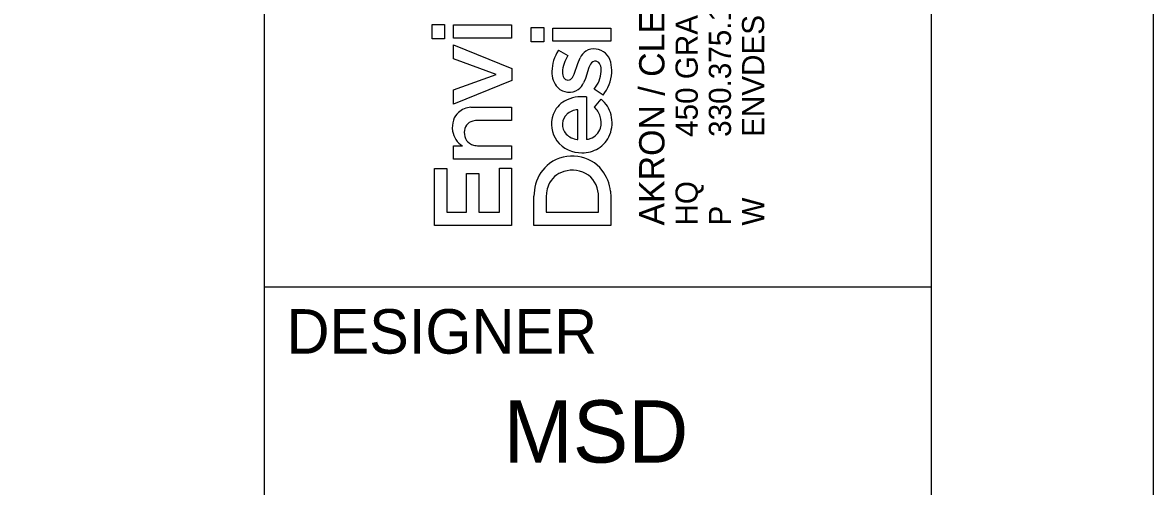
# Model space of a CAD drawing. Extents: x -6.7 to 34, y -1.6 to 22.
# Drawn here: x 31.456 to 34, y 2.552 to 3.594 of the extents above; entities that cross this region are included whole.
import ezdxf

# ---------------------------------------------------------------- set-up
doc = ezdxf.new("R2010")
doc.units = 0
for name, color, linetype in [('SH_Border', 7, 'Continuous'), ('SH_Cut_Line', 7, 'Continuous'), ('SH_Data', 7, 'Continuous')]:
    doc.layers.add(name, color=color, linetype=linetype)

msp = doc.modelspace()

# ---------------------------------------------------------------- linework, layer by layer
at = {"layer": 'SH_Border'}
for p, q in [((32, 0.5), (32, 21.5)), ((32, 3), (33.5, 3))]:
    msp.add_line(p, q, dxfattribs=at)
msp.add_lwpolyline([(1.5, 21.5), (33.5, 21.5), (33.5, 0.5), (1.5, 0.5)], close=True, dxfattribs=at)
at = {"layer": 'SH_Cut_Line'}
msp.add_lwpolyline([(0, 0), (34, 0), (34, 22), (0, 22)], close=True, dxfattribs=at)
at = {"layer": 'SH_Data'}
for p, q in [((32.3771, 3.5582), (32.3771, 3.5903)), ((32.3771, 3.5903), (32.4054, 3.5903)), ((32.4054, 3.5903), (32.4054, 3.5582)), ((32.4254, 3.5594), (32.4254, 3.5893)), ((32.4254, 3.5893), (32.5557, 3.5893)), ((32.5557, 3.5893), (32.5557, 3.5594)), ((32.6005, 3.5511), (32.6005, 3.5832)), ((32.6005, 3.5832), (32.6289, 3.5832)), ((32.6289, 3.5832), (32.6289, 3.5511)), ((32.6489, 3.5523), (32.6489, 3.5822)), ((32.6489, 3.5822), (32.7792, 3.5822)), ((32.7792, 3.5822), (32.7792, 3.5523)), ((32.4054, 3.5582), (32.3771, 3.5582)), ((32.5557, 3.5594), (32.4254, 3.5594)), ((32.4254, 3.5133), (32.4254, 3.5446)), ((32.4254, 3.5446), (32.5567, 3.4913)), ((32.6289, 3.5511), (32.6005, 3.5511)), ((32.7792, 3.5523), (32.6489, 3.5523)), ((32.5212, 3.478), (32.4254, 3.5133)), ((32.6615, 3.5321), (32.6827, 3.5203)), ((32.7048, 3.5026), (32.7104, 3.5153)), ((32.5567, 3.4913), (32.5567, 3.4644)), ((32.6967, 3.4787), (32.7048, 3.5026)), ((32.7298, 3.4933), (32.7221, 3.4688)), ((32.7334, 3.501), (32.7298, 3.4933)), ((32.4254, 3.4429), (32.5212, 3.478)), ((32.5567, 3.4644), (32.4254, 3.4109)), ((32.693, 3.4712), (32.6967, 3.4787)), ((32.7221, 3.4688), (32.7182, 3.4592)), ((32.4254, 3.4109), (32.4254, 3.4429)), ((32.7621, 3.4314), (32.742, 3.4447)), ((32.7245, 3.4275), (32.7246, 3.3319)), ((32.7423, 3.4046), (32.7577, 3.422)), ((32.4644, 3.404), (32.4729, 3.4044)), ((32.4729, 3.4044), (32.5557, 3.4044)), ((32.5557, 3.4044), (32.5557, 3.3746)), ((32.7049, 3.3318), (32.7049, 3.3983)), ((32.5557, 3.3746), (32.4814, 3.3746)), ((32.4254, 3.2875), (32.4254, 3.3173)), ((32.4254, 3.3173), (32.4455, 3.3173)), ((32.4822, 3.3173), (32.5557, 3.3173)), ((32.5557, 3.3173), (32.5557, 3.2876)), ((32.7036, 3.3317), (32.7049, 3.3318)), ((32.5557, 3.2876), (32.4254, 3.2875)), ((32.383, 3.1379), (32.383, 3.266)), ((32.383, 3.266), (32.4101, 3.266)), ((32.4101, 3.266), (32.4101, 3.1683)), ((32.5286, 3.1683), (32.5286, 3.2672)), ((32.5286, 3.2672), (32.5557, 3.2672)), ((32.5557, 3.2672), (32.5557, 3.1379)), ((32.455, 3.1683), (32.455, 3.2549)), ((32.455, 3.2549), (32.4822, 3.2549)), ((32.4822, 3.2549), (32.4822, 3.1683)), ((32.6347, 3.2118), (32.6341, 3.2023)), ((32.7785, 3.215), (32.7792, 3.2021)), ((32.6064, 3.138), (32.6064, 3.204)), ((32.6341, 3.2023), (32.6341, 3.1684)), ((32.7515, 3.1683), (32.7515, 3.2024)), ((32.7792, 3.2021), (32.7792, 3.138)), ((32.4101, 3.1683), (32.455, 3.1683)), ((32.4822, 3.1683), (32.5286, 3.1683)), ((32.6341, 3.1684), (32.7515, 3.1683)), ((32.5557, 3.1379), (32.383, 3.1379)), ((32.7792, 3.138), (32.6064, 3.138))]:
    msp.add_line(p, q, dxfattribs=at)
for points in [[(32.3771, 3.5582), (32.3771, 3.5903), (32.4054, 3.5903), (32.4054, 3.5582)], [(32.4254, 3.5594), (32.4254, 3.5893), (32.5557, 3.5893), (32.5557, 3.5594)], [(32.6005, 3.5511), (32.6005, 3.5832), (32.6289, 3.5832), (32.6289, 3.5511)], [(32.6489, 3.5523), (32.6489, 3.5822), (32.7792, 3.5822), (32.7792, 3.5523)], [(32.4254, 3.4109), (32.4254, 3.4429), (32.5212, 3.478), (32.4254, 3.5133), (32.4254, 3.5446), (32.5567, 3.4913), (32.5567, 3.4644)], [(32.383, 3.1379), (32.383, 3.266), (32.4101, 3.266), (32.4101, 3.1683), (32.455, 3.1683), (32.455, 3.2549), (32.4822, 3.2549), (32.4822, 3.1683), (32.5286, 3.1683), (32.5286, 3.2672), (32.5557, 3.2672), (32.5557, 3.1379)]]:
    msp.add_lwpolyline(points, close=True, dxfattribs=at)
for points in [[(32.6615, 3.5321), (32.6827, 3.5203)], [(32.693, 3.4712), (32.6967, 3.4787), (32.7048, 3.5026), (32.7104, 3.5153)], [(32.7334, 3.501), (32.7298, 3.4933), (32.7221, 3.4688), (32.7182, 3.4592)], [(32.7621, 3.4314), (32.742, 3.4447)], [(32.7245, 3.4275), (32.7246, 3.3319)], [(32.7423, 3.4046), (32.7577, 3.422)], [(32.4644, 3.404), (32.4729, 3.4044), (32.5557, 3.4044), (32.5557, 3.3746), (32.4814, 3.3746)], [(32.7036, 3.3317), (32.7049, 3.3318), (32.7049, 3.3983)], [(32.4254, 3.2875), (32.4254, 3.3173), (32.4455, 3.3173)], [(32.4822, 3.3173), (32.5557, 3.3173), (32.5557, 3.2876), (32.4254, 3.2875)], [(32.7785, 3.215), (32.7792, 3.2021), (32.7792, 3.138), (32.6064, 3.138)], [(32.6347, 3.2118), (32.6341, 3.2023), (32.6341, 3.1684), (32.7515, 3.1683), (32.7515, 3.2024)], [(32.6064, 3.138), (32.6064, 3.204)]]:
    msp.add_lwpolyline(points, dxfattribs=at)
for centre, radius, start, end in [((32.7364, 3.4826), 0.0897, 146.531, 178.7571), ((32.7364, 3.4826), 0.0897, 146.531, 178.7571), ((32.7452, 3.4789), 0.0749, 146.5112, 176.9101), ((32.7452, 3.4789), 0.0749, 146.5112, 176.9101), ((32.7466, 3.4971), 0.0405, 125.5118, 153.4159), ((32.7466, 3.4971), 0.0405, 125.5118, 153.4159), ((32.7406, 3.5026), 0.0326, 80.1719, 122.5197), ((32.7406, 3.5026), 0.0326, 80.1719, 122.5197), ((32.7428, 3.4982), 0.0367, 47.7934, 84.6892), ((32.7428, 3.4982), 0.0367, 47.7934, 84.6892), ((32.7379, 3.4946), 0.0427, 14.9966, 46.2063), ((32.7379, 3.4946), 0.0427, 14.9966, 46.2063), ((32.7438, 3.4963), 0.0114, 76.6609, 155.7053), ((32.7438, 3.4963), 0.0114, 76.6609, 155.7053), ((32.744, 3.4951), 0.0126, 21.5098, 78.5262), ((32.744, 3.4951), 0.0126, 21.5098, 78.5262), ((32.7259, 3.4877), 0.0321, 354.5726, 22.068), ((32.7259, 3.4877), 0.0321, 354.5726, 22.068), ((32.7104, 3.4867), 0.0712, 355.8306, 15.3914), ((32.7104, 3.4867), 0.0712, 355.8306, 15.3914), ((32.6967, 3.4824), 0.0501, 177.5366, 222.7932), ((32.6967, 3.4824), 0.0501, 177.5366, 222.7932), ((32.6931, 3.4823), 0.0228, 178.4747, 211.0868), ((32.6931, 3.4823), 0.0228, 178.4747, 211.0868), ((32.6833, 3.4767), 0.0115, 212.2368, 268.3777), ((32.6833, 3.4767), 0.0115, 212.2368, 268.3777), ((32.6834, 3.4759), 0.0107, 267.716, 333.7337), ((32.6834, 3.4759), 0.0107, 267.716, 333.7337), ((32.6825, 3.4915), 0.0757, 321.811, 354.7969), ((32.6825, 3.4915), 0.0757, 321.811, 354.7969), ((32.6895, 3.4882), 0.0922, 321.9777, 355.8738), ((32.6895, 3.4882), 0.0922, 321.9777, 355.8738), ((32.686, 3.4753), 0.0375, 225.9854, 302.4797), ((32.686, 3.4753), 0.0375, 225.9854, 302.4797), ((32.681, 3.4758), 0.0408, 308.0877, 335.9874), ((32.681, 3.4758), 0.0408, 308.0877, 335.9874), ((32.7024, 3.3691), 0.0558, 118.8308, 160.6244), ((32.7024, 3.3691), 0.0558, 118.8308, 160.6244), ((32.7152, 3.3441), 0.0838, 83.615, 118.2876), ((32.7152, 3.3441), 0.0838, 83.615, 118.2876), ((32.7174, 3.3717), 0.0644, 13.5336, 51.3615), ((32.7174, 3.3717), 0.0644, 13.5336, 51.3615), ((32.4635, 3.3626), 0.0402, 132.2219, 161.6818), ((32.4635, 3.3626), 0.0402, 132.2219, 161.6818), ((32.4687, 3.3543), 0.0499, 94.9696, 130.2225), ((32.4687, 3.3543), 0.0499, 94.9696, 130.2225), ((32.7104, 3.3661), 0.0644, 160.5201, 215.7831), ((32.7104, 3.3661), 0.0644, 160.5201, 215.7831), ((32.7005, 3.3663), 0.0298, 132.9851, 177.179), ((32.7005, 3.3663), 0.0298, 132.9851, 177.179), ((32.7079, 3.3561), 0.0424, 94.008, 130.8817), ((32.7079, 3.3561), 0.0424, 94.008, 130.8817), ((32.7038, 3.3656), 0.0549, 19.0357, 45.4406), ((32.7038, 3.3656), 0.0549, 19.0357, 45.4406), ((32.7107, 3.3697), 0.047, 344.6059, 17.007), ((32.7107, 3.3697), 0.047, 344.6059, 17.007), ((32.7064, 3.3692), 0.0758, 339.3542, 13.3785), ((32.7064, 3.3692), 0.0758, 339.3542, 13.3785), ((32.4787, 3.3582), 0.056, 162.2736, 187.7919), ((32.4787, 3.3582), 0.056, 162.2736, 187.7919), ((32.4748, 3.3487), 0.025, 103.6865, 182.2187), ((32.4748, 3.3487), 0.025, 103.6865, 182.2187), ((32.4811, 3.3286), 0.046, 89.6049, 105.3284), ((32.4811, 3.3286), 0.046, 89.6049, 105.3284), ((32.7017, 3.365), 0.0311, 175.0013, 223.283), ((32.7017, 3.365), 0.0311, 175.0013, 223.283), ((32.4703, 3.358), 0.0476, 188.962, 238.7037), ((32.4703, 3.358), 0.0476, 188.962, 238.7037), ((32.4773, 3.3456), 0.0276, 175.5854, 255.1439), ((32.4773, 3.3456), 0.0276, 175.5854, 255.1439), ((32.7089, 3.3736), 0.0423, 225.0619, 262.7974), ((32.7089, 3.3736), 0.0423, 225.0619, 262.7974), ((32.7247, 3.3522), 0.0202, 269.7003, 294.8711), ((32.7247, 3.3522), 0.0202, 269.7003, 294.8711), ((32.7224, 3.3671), 0.035, 288.0077, 343.5508), ((32.7224, 3.3671), 0.035, 288.0077, 343.5508), ((32.7189, 3.3652), 0.0626, 300.9427, 338.7323), ((32.7189, 3.3652), 0.0626, 300.9427, 338.7323), ((32.4818, 3.3595), 0.0422, 254.0916, 270.5284), ((32.4818, 3.3595), 0.0422, 254.0916, 270.5284), ((32.7125, 3.3705), 0.0687, 217.7452, 271.6543), ((32.7125, 3.3705), 0.0687, 217.7452, 271.6543), ((32.7155, 3.3724), 0.0706, 269.2048, 300.3341), ((32.7155, 3.3724), 0.0706, 269.2048, 300.3341), ((32.6923, 3.2079), 0.0864, 81.194, 125.9984), ((32.6923, 3.2079), 0.0864, 81.194, 125.9984), ((32.6946, 3.2113), 0.0827, 37.8521, 82.402), ((32.6946, 3.2113), 0.0827, 37.8521, 82.402), ((32.6939, 3.2089), 0.0865, 127.2362, 165.148), ((32.6939, 3.2089), 0.0865, 127.2362, 165.148), ((32.6889, 3.2078), 0.054, 106.1881, 157.3861), ((32.6889, 3.2078), 0.054, 106.1881, 157.3861), ((32.6928, 3.1986), 0.0639, 55.6727, 107.2093), ((32.6928, 3.1986), 0.0639, 55.6727, 107.2093), ((32.6859, 3.2057), 0.0931, 5.7333, 37.304), ((32.6859, 3.2057), 0.0931, 5.7333, 37.304), ((32.7143, 3.2028), 0.1078, 164.7861, 179.3704), ((32.7143, 3.2028), 0.1078, 164.7861, 179.3704), ((32.6929, 3.205), 0.0587, 357.4662, 52.2665), ((32.6929, 3.205), 0.0587, 357.4662, 52.2665), ((32.6983, 3.2039), 0.0641, 157.3571, 172.9275), ((32.6983, 3.2039), 0.0641, 157.3571, 172.9275)]:
    msp.add_arc(centre, radius, start, end, dxfattribs=at)

# ---------------------------------------------------------------- texts
for s, height, p in [('450 GRANT ST., AKRON, OH  44311', 0.049846, (32.9749, 3.3374)), ('AKRON / CLEVELAND / COLUMBUS', 0.056969, (32.9001, 3.138)), ('ENVDESIGNGROUP.COM', 0.049846, (33.1244, 3.3374)), ('330.375.1390', 0.049846, (33.0497, 3.3374)), ('HQ ', 0.04985, (32.9749, 3.138)), ('W', 0.0498, (33.1244, 3.138)), ('P', 0.0498, (33.0497, 3.138))]:
    msp.add_text(s, height=height, rotation=90, dxfattribs=at).set_placement(p)
for s, height, p in [('DESIGNER', 0.1, (32.05, 2.85)), ('MSD', 0.14, (32.5379, 2.605))]:
    msp.add_text(s, height=height, dxfattribs=at).set_placement(p)

doc.saveas('drawing.dxf')
